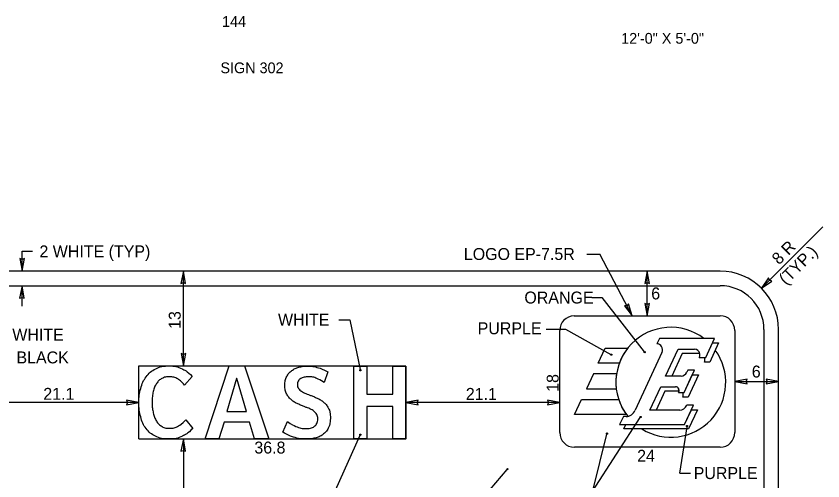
# Model space of a CAD drawing. Extents: x 60712 to 61344, y 9358 to 10016.
# Drawn here: x 60817.5 to 61027.6, y 9523.5 to 9644.5 of the extents above; entities that cross this region are included whole.
import ezdxf

# ---------------------------------------------------------------- set-up
doc = ezdxf.new("R2010")
doc.units = 0
for name, color, linetype in [('1', 7, 'Continuous'), ('52', 7, 'Continuous'), ('Default', 7, 'Continuous'), ('SignPanel', 7, 'Continuous')]:
    doc.layers.add(name, color=color, linetype=linetype)

msp = doc.modelspace()

# ---------------------------------------------------------------- linework, layer by layer
at = {"layer": '1'}
for p, q in [((61027.65, 9589.65), (61011.65, 9573.65)), ((60819.02, 9578.14), (60819.02, 9583.28)), ((60819.02, 9583.28), (60821.75, 9583.28)), ((60966.2, 9582.54), (60969.53, 9582.54)), ((60977.99, 9566.46), (60969.53, 9582.54)), ((60981.88, 9566.46), (60981.88, 9578.1)), ((60819.02, 9568.93), (60819.02, 9574.25)), ((60967.5, 9571.25), (60970.05, 9571.25)), ((60970.05, 9571.25), (60981.13, 9557.11)), ((60901.57, 9565.45), (60904.42, 9565.45)), ((60904.42, 9565.45), (60907.15, 9552.45)), ((60955.54, 9562.97), (60960.6, 9562.97)), ((60960.6, 9562.97), (60972.45, 9556.4)), ((61004.7, 9549.36), (61016.1, 9549.36)), ((60967.73, 9520.86), (60980.08, 9540)), ((60990.35, 9525.51), (60992.26, 9537.59)), ((60900.69, 9521.08), (60907.15, 9535.36)), ((60967.73, 9520.86), (60971.4, 9535.64)), ((60940.98, 9521.26), (60945.38, 9526.45)), ((60990.35, 9525.51), (60993.2, 9525.51))]:
    msp.add_line(p, q, dxfattribs=at)
for centre, major_axis, ratio in [((60972.53, 9556.34), (0, 0.157), 0.906668), ((60981.23, 9557), (0, 0.157), 0.906668), ((60907.15, 9552.29), (0.164, 0), 0.960359), ((60980.18, 9540.11), (0, 0.157), 0.906668), ((60992.26, 9537.75), (0, 0.157), 0.906668), ((60907.15, 9535.51), (0.164, 0), 0.960359), ((60971.4, 9535.8), (0, 0.157), 0.906668), ((60945.49, 9526.55), (0, 0.157), 0.906668)]:
    msp.add_ellipse(centre, major_axis=major_axis, ratio=ratio, dxfattribs=at)
at = {"layer": '52'}
for p, q in [((60819.02, 9581.12), (60818.42, 9581.36)), ((60818.42, 9581.36), (60819.02, 9578.14)), ((60819.02, 9578.14), (60819.64, 9581.36)), ((60819.64, 9581.36), (60819.02, 9581.12)), ((60861.05, 9578.1), (60860.42, 9574.88)), ((60861.65, 9574.88), (60861.05, 9578.1)), ((60981.88, 9578.1), (60981.26, 9574.88)), ((60982.48, 9574.88), (60981.88, 9578.1)), ((60860.42, 9574.88), (60861.05, 9575.12)), ((60861.05, 9575.12), (60861.65, 9574.88)), ((60981.26, 9574.88), (60981.88, 9575.12)), ((60981.88, 9575.12), (60982.48, 9574.88)), ((61013.51, 9576.35), (61011.65, 9573.65)), ((61011.65, 9573.65), (61014.37, 9575.49)), ((61013.76, 9575.76), (61013.51, 9576.35)), ((61014.37, 9575.49), (61013.76, 9575.76)), ((60819.02, 9574.25), (60818.39, 9571.03)), ((60819.62, 9571.03), (60819.02, 9574.25)), ((60818.39, 9571.03), (60819.02, 9571.27)), ((60819.02, 9571.27), (60819.62, 9571.03)), ((60976.61, 9569.09), (60975.96, 9569.03)), ((60975.96, 9569.03), (60977.99, 9566.46)), ((60977.04, 9569.6), (60976.61, 9569.09)), ((60977.99, 9566.46), (60977.04, 9569.6)), ((60981.88, 9569.44), (60981.28, 9569.68)), ((60981.28, 9569.68), (60981.88, 9566.46)), ((60981.88, 9566.46), (60982.5, 9569.68)), ((60982.5, 9569.68), (60981.88, 9569.44)), ((60861.05, 9556.38), (60860.45, 9556.62)), ((60860.45, 9556.62), (60861.05, 9553.4)), ((60861.05, 9553.4), (60861.67, 9556.62)), ((60861.67, 9556.62), (60861.05, 9556.38)), ((61007.93, 9549.96), (61004.7, 9549.36)), ((61007.68, 9549.36), (61007.93, 9549.96)), ((61016.1, 9549.36), (61012.88, 9549.98)), ((61012.88, 9549.98), (61013.13, 9549.36)), ((61004.7, 9549.36), (61007.93, 9548.74)), ((61007.93, 9548.74), (61007.68, 9549.36)), ((61013.13, 9549.36), (61012.88, 9548.76)), ((61012.88, 9548.76), (61016.1, 9549.36)), ((60849.48, 9543.9), (60846.26, 9544.52)), ((60846.26, 9544.52), (60846.5, 9543.9)), ((60846.5, 9543.9), (60846.26, 9543.3)), ((60846.26, 9543.3), (60849.48, 9543.9)), ((60922.24, 9544.48), (60919.01, 9543.88)), ((60919.01, 9543.88), (60922.24, 9543.26)), ((60921.99, 9543.88), (60922.24, 9544.48)), ((60922.24, 9543.26), (60921.99, 9543.88)), ((60959.1, 9543.88), (60955.88, 9544.5)), ((60955.88, 9544.5), (60956.13, 9543.88)), ((60956.13, 9543.88), (60955.88, 9543.28)), ((60955.88, 9543.28), (60959.1, 9543.88)), ((60861.05, 9534.4), (60860.42, 9531.18)), ((60861.65, 9531.18), (60861.05, 9534.4)), ((60860.42, 9531.18), (60861.05, 9531.42)), ((60861.05, 9531.42), (60861.65, 9531.18))]:
    msp.add_line(p, q, dxfattribs=at)
at = {"layer": 'Default'}
for p, q in [((60849.48, 9553.4), (60919.01, 9553.4)), ((60849.48, 9534.4), (60849.48, 9553.4)), ((60919.01, 9534.33), (60919.01, 9553.19)), ((60849.48, 9534.4), (60919.01, 9534.4))]:
    msp.add_line(p, q, dxfattribs=at)
at = {"layer": 'SignPanel'}
for p, q in [((61000.9, 9578.1), (60757.7, 9578.1)), ((60861.05, 9553.4), (60861.05, 9578.1)), ((60757.7, 9574.3), (61000.9, 9574.3)), ((60962.86, 9566.46), (61000.9, 9566.46)), ((60959.1, 9536.06), (60959.1, 9562.66)), ((61004.7, 9562.66), (61004.7, 9536.06)), ((61012.3, 9562.9), (61012.3, 9479.3)), ((61016.1, 9479.3), (61016.1, 9562.9)), ((60985.05, 9560.58), (60984.4, 9559.18)), ((60999.43, 9560.58), (60985.05, 9560.58)), ((60997.13, 9555.6), (60999.43, 9560.58)), ((60997.13, 9555.6), (60998.89, 9559.4)), ((61000.48, 9559.4), (60998.18, 9554.42)), ((60998.89, 9559.4), (61000.48, 9559.4)), ((60969.14, 9554.1), (60970.95, 9558.03)), ((60970.95, 9558.03), (60976.82, 9558.03)), ((60985.72, 9556.9), (60978.79, 9541.9)), ((60986.69, 9550.79), (60989.92, 9557.78)), ((60986.69, 9550.79), (60989.92, 9557.78)), ((60990.98, 9556.61), (60988.29, 9550.79)), ((60989.92, 9557.78), (60994.24, 9557.78)), ((60989.92, 9557.78), (60994.24, 9557.78)), ((60995.56, 9556.61), (60990.98, 9556.61)), ((60974.61, 9554.1), (60969.14, 9554.1)), ((60974.61, 9554.1), (60974.61, 9554.1)), ((60995.44, 9555.6), (60997.13, 9555.6)), ((60998.18, 9554.42), (60996.79, 9554.42)), ((60996.87, 9555.6), (60997.13, 9555.6)), ((60991.48, 9546.48), (60994.17, 9552.3)), ((60992.47, 9552.3), (60992.25, 9551.8)), ((60994.17, 9552.3), (60992.47, 9552.3)), ((60967.86, 9551.35), (60966.05, 9547.42)), ((60973.9, 9551.35), (60967.86, 9551.35)), ((60990.74, 9550.79), (60986.69, 9550.79)), ((60988.29, 9550.79), (60986.69, 9550.79)), ((60991.48, 9546.48), (60993.62, 9551.12)), ((60995.22, 9551.12), (60992.53, 9545.3)), ((60993.62, 9551.12), (60995.22, 9551.12)), ((60982.59, 9541.92), (60985.4, 9547.99)), ((60982.59, 9541.92), (60985.4, 9547.99)), ((60985.4, 9547.99), (60989.3, 9547.99)), ((60985.4, 9547.99), (60989.3, 9547.99)), ((60966.05, 9547.42), (60973.84, 9547.42)), ((60986.45, 9546.81), (60984.19, 9541.92)), ((60990.17, 9546.81), (60986.45, 9546.81)), ((60990.04, 9546.48), (60991.48, 9546.48)), ((60991.23, 9546.48), (60991.48, 9546.48)), ((60849.48, 9543.9), (60808.53, 9543.9)), ((60959.1, 9543.88), (60919.01, 9543.88)), ((60962.96, 9540.74), (60964.78, 9544.67)), ((60964.78, 9544.67), (60974.46, 9544.67)), ((60992.53, 9545.3), (60991.14, 9545.3)), ((60990.36, 9541.92), (60982.59, 9541.92)), ((60984.19, 9541.92), (60982.59, 9541.92)), ((60990.36, 9541.92), (60990.36, 9541.92)), ((60991.62, 9538.19), (60993.93, 9543.18)), ((60991.62, 9538.19), (60993.39, 9542)), ((60993.93, 9543.18), (60992.23, 9543.18)), ((60994.98, 9542), (60992.68, 9537.01)), ((60993.39, 9542), (60994.98, 9542)), ((60976.47, 9540.74), (60962.96, 9540.74)), ((60975.67, 9540.26), (60974.7, 9538.19)), ((60976.38, 9540.26), (60975.67, 9540.26)), ((60974.7, 9538.19), (60991.62, 9538.19)), ((60975.76, 9537.01), (60976.3, 9538.19)), ((60976.3, 9538.19), (60991.62, 9538.19)), ((60992.68, 9537.01), (60975.76, 9537.01)), ((60861.05, 9534.4), (60861.05, 9507.75)), ((61000.9, 9532.26), (60962.91, 9532.26))]:
    msp.add_line(p, q, dxfattribs=at)
for points in [[(60879.62, 9534.4), (60878.24, 9538.73), (60871.69, 9538.73), (60870.3, 9534.4), (60866.74, 9534.4), (60872.96, 9553.4), (60876.95, 9553.4), (60883.3, 9534.4), (60879.62, 9534.4)], [(60898.68, 9551.86), (60897.7, 9549.08)], [(60915.61, 9534.4), (60915.61, 9542.84), (60908.85, 9542.84), (60908.85, 9534.4), (60905.45, 9534.4), (60905.45, 9553.35), (60908.85, 9553.35), (60908.85, 9546.03), (60915.61, 9546.03), (60915.61, 9553.35), (60919.01, 9553.35), (60919.01, 9534.4), (60915.61, 9534.4)], [(60863.35, 9550.7), (60861.38, 9548.42)], [(60875, 9550.18), (60874.91, 9550.18), (60872.37, 9541.58), (60877.54, 9541.58), (60875, 9550.18)], [(60861.72, 9539.39), (60863.49, 9537.09)], [(60886.93, 9536.21), (60888.19, 9538.97)]]:
    msp.add_lwpolyline(points, dxfattribs=at)
for centre, radius, start, end in [((61000.9, 9562.9), 15.2, 0, 90), ((61000.9, 9562.9), 11.4, 0, 90), ((60962.9, 9562.66), 3.8, 90.6597, 180), ((61000.9, 9562.66), 3.8, 0, 90), ((60988.04, 9549.16), 14.31, 52.9575, 218.2327), ((60988.04, 9549.16), 14.31, 141.6926, 159.8015), ((60988.04, 9549.16), 14.31, 238.1326, 35.91), ((60988.04, 9549.16), 14.31, 171.2075, 186.983), ((60988.04, 9549.16), 14.31, 198.3, 216.0576), ((60962.9, 9536.06), 3.8, 180, 270), ((61000.9, 9536.06), 3.8, 270, 360)]:
    msp.add_arc(centre, radius, start, end, dxfattribs=at)
for centre, major_axis, start_param, end_param in [((60984.45, 9557.61), (0, 1.57), 4.241328, 6.314398), ((60994.24, 9556.29), (0, 1.49), 4.227342, 6.283185), ((60994.24, 9556.29), (0, 1.49), 4.924621, 6.283185), ((60995.59, 9555.11), (0, 1.49), 4.227342, 5.041732), ((60990.74, 9552.65), (0, 1.87), 3.141593, 4.241405), ((60989.3, 9547), (0, 0.982), 4.144801, 6.283185), ((60989.3, 9547), (0, 0.982), 4.51088, 6.283185), ((60989.94, 9545.99), (0, 1.49), 4.227342, 5.041732), ((60976.37, 9543.25), (0, 2.99), 3.141593, 4.241135), ((60990.36, 9544.25), (0, 2.33), 3.141593, 4.232591)]:
    msp.add_ellipse(centre, major_axis=major_axis, ratio=0.906668, start_param=start_param, end_param=end_param, dxfattribs=at)
for points in [[(60863.49, 9537.09), (60862.22, 9535.8), (60860.72, 9535.1), (60859.22, 9534.4), (60857.38, 9534.4), (60855.3, 9534.4), (60853.81, 9535.12), (60852.32, 9535.84), (60851.35, 9537.11), (60850.38, 9538.39), (60849.93, 9540.14), (60849.48, 9541.89), (60849.48, 9543.95), (60849.48, 9545.86), (60849.95, 9547.57), (60850.42, 9549.28), (60851.38, 9550.58), (60852.35, 9551.88), (60853.84, 9552.64), (60855.33, 9553.4), (60857.39, 9553.4), (60859.19, 9553.4), (60860.6, 9552.73), (60862, 9552.06), (60863.35, 9550.7)], [(60888.19, 9538.97), (60889.26, 9538.18), (60890.45, 9537.63), (60891.64, 9537.08), (60893, 9537.08), (60893.59, 9537.08), (60894.14, 9537.21), (60894.7, 9537.34), (60895.13, 9537.63), (60895.56, 9537.93), (60895.82, 9538.42), (60896.08, 9538.9), (60896.08, 9539.64), (60896.08, 9540.29), (60895.81, 9540.76), (60895.54, 9541.24), (60895.08, 9541.6), (60894.62, 9541.96), (60894.02, 9542.24), (60893.42, 9542.51), (60892.74, 9542.75), (60891.84, 9543.1), (60890.91, 9543.52), (60889.98, 9543.93), (60889.22, 9544.56), (60888.46, 9545.19), (60887.98, 9546.1), (60887.5, 9547.01), (60887.5, 9548.36), (60887.5, 9549.69), (60887.99, 9550.63), (60888.48, 9551.57), (60889.3, 9552.18), (60890.12, 9552.79), (60891.17, 9553.07), (60892.22, 9553.36), (60893.35, 9553.36), (60894.84, 9553.36), (60896.14, 9552.96), (60897.44, 9552.56), (60898.68, 9551.86)], [(60861.38, 9548.42), (60860.92, 9548.95), (60860.48, 9549.36), (60860.04, 9549.76), (60859.57, 9550.04), (60859.1, 9550.31), (60858.59, 9550.45), (60858.07, 9550.59), (60857.47, 9550.59), (60856.33, 9550.59), (60855.48, 9550.14), (60854.64, 9549.69), (60854.07, 9548.83), (60853.5, 9547.98), (60853.21, 9546.75), (60852.93, 9545.51), (60852.93, 9543.95), (60852.93, 9542.68), (60853.15, 9541.48), (60853.37, 9540.27), (60853.89, 9539.31), (60854.42, 9538.36), (60855.29, 9537.78), (60856.17, 9537.2), (60857.47, 9537.2), (60858.72, 9537.2), (60859.71, 9537.74), (60860.69, 9538.28), (60861.72, 9539.39)], [(60897.7, 9549.08), (60896.74, 9549.78), (60895.77, 9550.18), (60894.81, 9550.58), (60893.59, 9550.58), (60893.02, 9550.58), (60892.51, 9550.48), (60892, 9550.38), (60891.62, 9550.13), (60891.23, 9549.88), (60891, 9549.48), (60890.77, 9549.07), (60890.77, 9548.48), (60890.77, 9547.93), (60891.06, 9547.53), (60891.36, 9547.12), (60891.86, 9546.8), (60892.35, 9546.48), (60893, 9546.22), (60893.65, 9545.96), (60894.35, 9545.69), (60895.23, 9545.35), (60896.12, 9544.92), (60897.02, 9544.49), (60897.74, 9543.84), (60898.46, 9543.2), (60898.91, 9542.26), (60899.36, 9541.32), (60899.36, 9539.97)], [(60899.36, 9539.97), (60899.36, 9538.5), (60898.89, 9537.44), (60898.42, 9536.39), (60897.59, 9535.71), (60896.76, 9535.03), (60895.63, 9534.72), (60894.49, 9534.4), (60893.16, 9534.4), (60891.36, 9534.4), (60889.86, 9534.84), (60888.37, 9535.29), (60886.93, 9536.21)]]:
    msp.add_open_spline(points, degree=3, dxfattribs=at)

# ---------------------------------------------------------------- texts
at = {"layer": '1'}
for s, height, p in [('144', 2.8, (60871.12, 9641.68)), ('12\'-0" X 5\'-0"', 2.8, (60975.11, 9637.3)), ('SIGN 302', 2.8, (60870.71, 9629.62)), ('2 WHITE (TYP)', 3.1111, (60823.56, 9581.67)), ('LOGO EP-7.5R', 3.1111, (60934.12, 9580.99)), ('ORANGE', 3.111, (60949.89, 9569.66)), ('6', 3.11, (60982.94, 9570.73)), ('WHITE', 3.111, (60885.71, 9563.89)), ('PURPLE', 3.111, (60937.72, 9561.66)), ('WHITE', 3.111, (60816.49, 9559.98)), ('BLACK', 3.111, (60817.57, 9554.07)), ('6', 3.11, (61009.13, 9550.39)), ('21.1', 3.111, (60824.57, 9544.59)), ('21.1', 3.111, (60934.63, 9544.57)), ('36.8', 3.111, (60879.55, 9530.6)), ('24', 3.111, (60979.26, 9528.46)), ('PURPLE', 3.111, (60994, 9523.96))]:
    msp.add_text(s, height=height, dxfattribs=at).set_placement(p)
for s, rotation, p in [('8 R', 45, (61016.23, 9579.58)), ('(TYP.)', 45, (61018.05, 9574.31)), ('13', 90, (60860.36, 9563.05)), ('18', 90, (60958.81, 9546.67))]:
    msp.add_text(s, height=3.111, rotation=rotation, dxfattribs=at).set_placement(p)

doc.saveas('drawing.dxf')
